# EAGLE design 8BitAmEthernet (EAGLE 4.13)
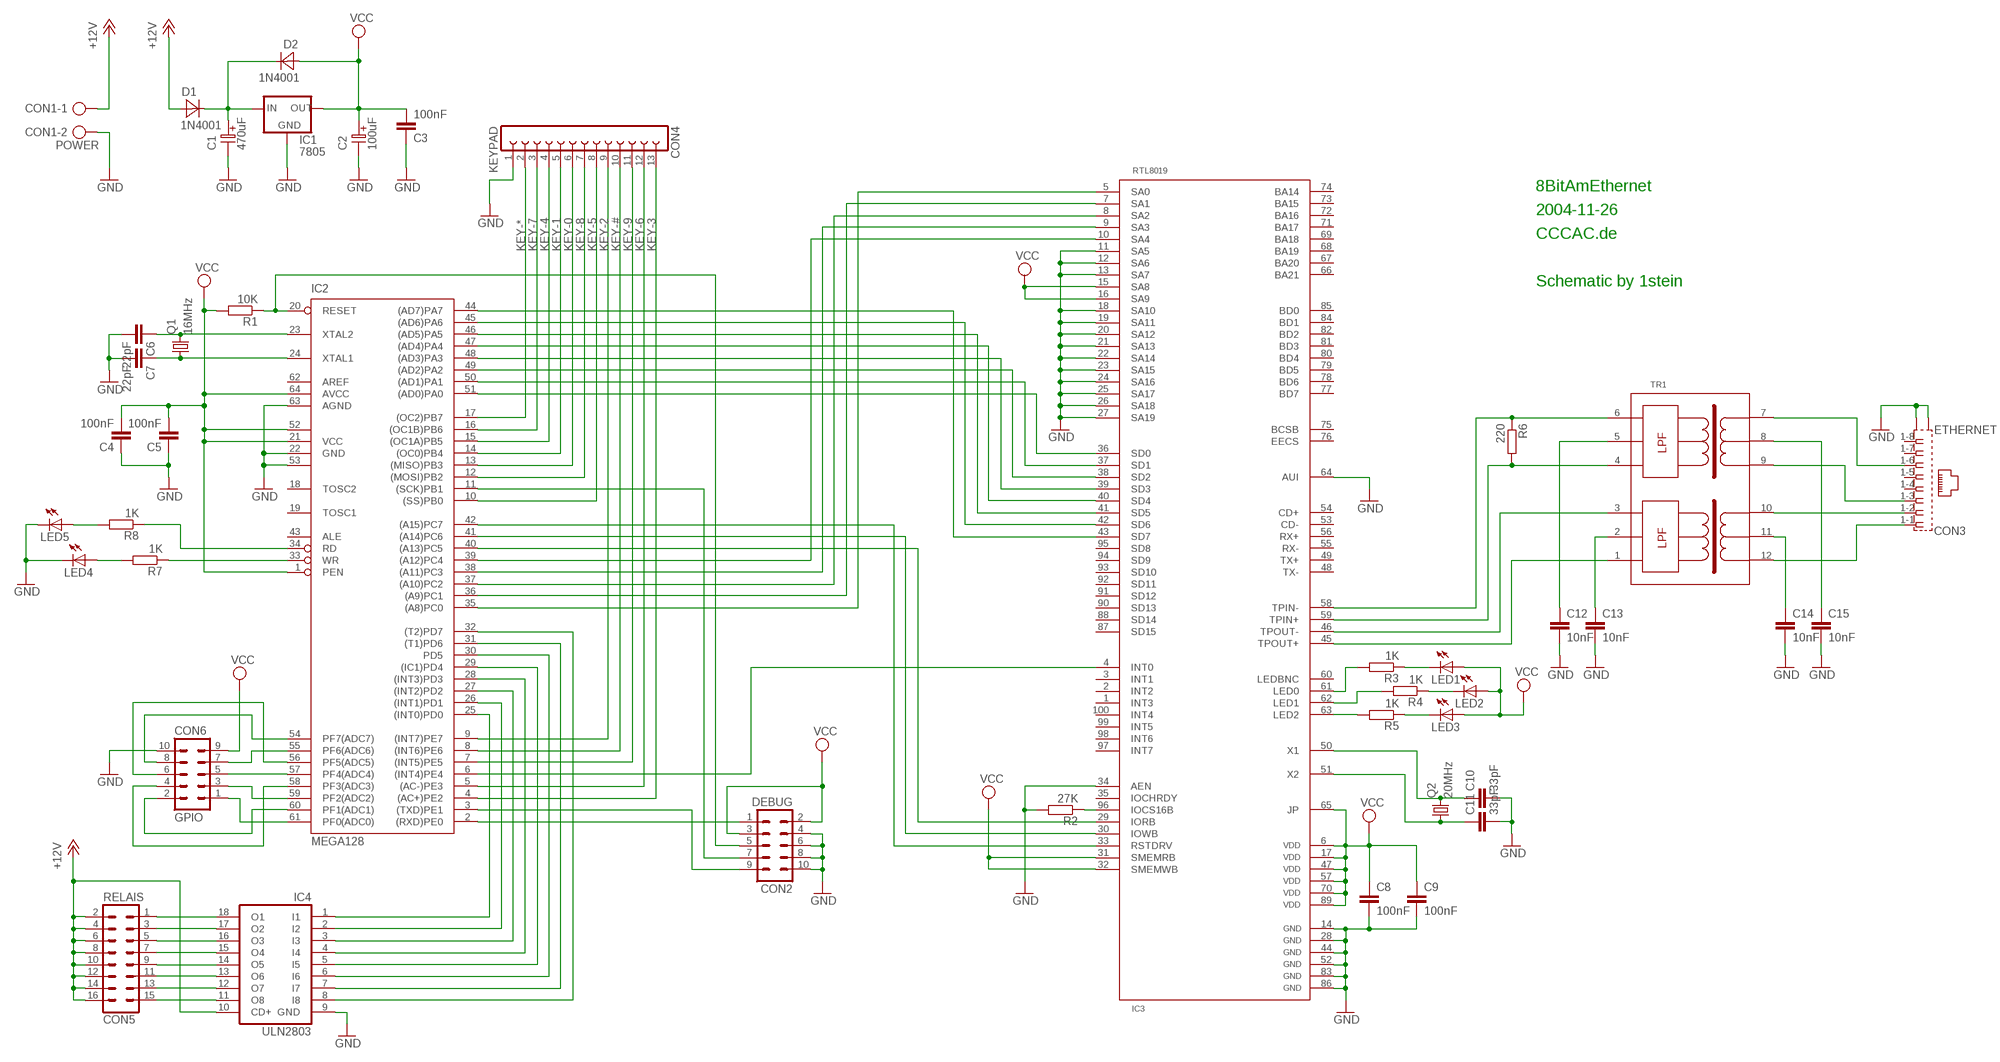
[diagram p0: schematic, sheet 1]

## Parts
C1  470uF  ELC-5  [ES-5]
C2  100uF  ELC-5  [ES-5]
C3  100nF  C-EUC0805  [C0805]
C4  100nF  C-EUC0805  [C0805]
C5  100nF  C-EUC0805  [C0805]
C6  22pF  C-EUC0805  [C0805]
C7  22pF  C-EUC0805  [C0805]
C8  100nF  C-EUC0805  [C0805]
C9  100nF  C-EUC0805  [C0805]
C10  33pF  C-EUC0805  [C0805]
C11  33pF  C-EUC0805  [C0805]
C12  10nF  C-EUC0805  [C0805]
C13  10nF  C-EUC0805  [C0805]
C14  10nF  C-EUC0805  [C0805]
C15  10nF  C-EUC0805  [C0805]
CON1  POWER  AK500/2  [AK500/2]
CON2  DEBUG  ML10  [ML10]
CON3  ETHERNET  557786-1  [557786-1]
CON4  KEYPAD  FE13-1  [FE13]
CON5  RELAIS  ML16  [ML16]
CON6  GPIO  ML10  [ML10]
D1  1N4001  DIODE-7,5  [D-7,5]
D2  1N4001  DIODE-7,5  [D-7,5]
IC1  7805  78XXL  [78XXL]
IC2  MEGA128  MEGA103  [TQFP64]
IC3  RTL8019  [TQPF100]
IC4  ULN2803  ULN2803A  [DIL18]
LED1  LED3MM  [LED3MM]
LED2  LED3MM  [LED3MM]
LED3  LED3MM  [LED3MM]
LED4  LED3MM  [LED3MM]
LED5  LED3MM  [LED3MM]
Q1  16MHz  CRYTALHC49S  [HC49/S]
Q2  20MHz  CRYTALHC49S  [HC49/S]
R1  10K  R-EU_R0805  [R0805]
R2  27K  R-EU_R0805  [R0805]
R3  1K  R-EU_R0805  [R0805]
R4  1K  R-EU_R0805  [R0805]
R5  1K  R-EU_R0805  [R0805]
R6  220  R-EU_R0805  [R0805]
R7  1K  R-EU_R0805  [R0805]
R8  1K  R-EU_R0805  [R0805]
TR1  FB2022  20F001  [DIL16/12]

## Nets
+12V: CON1.1 CON5.2 CON5.4 CON5.6 CON5.8 CON5.10 CON5.12 CON5.14 CON5.16 D1.1(A) IC4.10(CD+)
GND: C1.2 C2.2 C3.1 C4.1 C5.1 C6.2 C7.2 C8.2 C9.2 C10.2 C11.2 C12.2 C13.2 C14.2 C15.2 CON1.2 CON2.4 CON2.6 CON2.8 CON2.10 CON3.G1(S2) CON3.G2(S1) CON4.1 CON6.10 IC1.GND IC2.22(GND) IC2.53(GND1) IC2.63(AGND) IC3.11(SA5) IC3.12(SA6) IC3.13(SA7) IC3.14(G1) IC3.18(SA10) IC3.19(SA11) IC3.20(SA12) IC3.21(SA13) IC3.22(SA14) IC3.23(SA15) IC3.24(SA16) IC3.25(SA17) IC3.26(SA18) IC3.27(SA19) IC3.28(G2) IC3.34(AEN) IC3.44(G3) IC3.52(G4) IC3.64(AUI) IC3.83(G5) IC3.86(G6) IC4.9(GND) LED4.K(C) LED5.K(C) R2.2
KEY-0: CON4.6 IC2.13((MISO)PB3)
KEY-1: CON4.5 IC2.14((OC0)PB4)
KEY-2: CON4.9 IC2.9((INT7)PE7)
KEY-3: CON4.13 IC2.4((AC+)PE2)
KEY-4: CON4.4 IC2.15((OC1A)PB5)
KEY-5: CON4.8 IC2.10((SS)PB0)
KEY-6: CON4.12 IC2.5((AC-)PE3)
KEY-7: CON4.3 IC2.16((OC1B)PB6)
KEY-8: CON4.7 IC2.12((MOSI)PB2)
KEY-9: CON4.11 IC2.7((INT5)PE5)
KEY-#: CON4.10 IC2.8((INT6)PE6)
KEY-*: CON4.2 IC2.17((OC2)PB7)
N$1: C1.1 D1.2(K) D2.2(K) IC1.IN
N$2: C6.1 IC2.23(XTAL2) Q1.2
N$3: C7.1 IC2.24(XTAL1) Q1.1
N$5: CON6.7 IC2.55(PF6(ADC6))
N$7: CON6.4 IC2.58(PF3(ADC3))
N$8: IC3.96(IOCS16B) R2.1
N$9: IC3.61(LED0) R3.2
N$10: IC3.62(LED1) R4.2
N$11: C10.1 IC3.50(X1) Q2.2
N$12: C11.1 IC3.51(X2) Q2.1
N$13: IC3.63(LED2) R5.2
N$14: LED3.K(C) R5.1
N$15: LED2.K(C) R4.1
N$16: LED1.K(C) R3.1
N$17: IC2.35((A8)PC0) IC3.5(SA0)
N$18: CON3.1-1 TR1.12
N$19: IC3.45(TPOUT+) TR1.1
N$20: IC3.46(TPOUT-) TR1.3
N$21: IC3.59(TPIN+) R6.2 TR1.4
N$22: IC3.58(TPIN-) R6.1 TR1.6
N$23: C13.1 TR1.2
N$24: C12.1 TR1.5
N$25: C15.1 TR1.8
N$26: C14.1 TR1.11
N$27: CON3.1-2 TR1.10
N$28: CON3.1-3 TR1.9
N$29: CON3.1-6 TR1.7
N$30: IC2.36((A9)PC1) IC3.7(SA1)
N$31: IC2.37((A10)PC2) IC3.8(SA2)
N$32: IC2.38((A11)PC3) IC3.9(SA3)
N$33: IC2.39((A12)PC4) IC3.10(SA4)
N$34: IC2.40((A13)PC5) IC3.29(IORB)
N$35: IC2.41((A14)PC6) IC3.30(IOWB)
N$36: IC2.42((A15)PC7) IC3.33(RSTDRV)
N$37: IC2.44((AD7)PA7) IC3.43(SD7)
N$38: IC2.45((AD6)PA6) IC3.42(SD6)
N$39: IC2.46((AD5)PA5) IC3.41(SD5)
N$40: IC2.47((AD4)PA4) IC3.40(SD4)
N$41: IC2.48((AD3)PA3) IC3.39(SD3)
N$42: IC2.49((AD2)PA2) IC3.38(SD2)
N$43: IC2.50((AD1)PA1) IC3.37(SD1)
N$44: IC2.51((AD0)PA0) IC3.36(SD0)
N$45: IC2.6((INT4)PE4) IC3.4(INT0)
N$46: IC2.34(RD) R8.1
N$47: LED5.A R8.2
N$48: LED4.A R7.2
N$49: IC2.33(WR) R7.1
N$50: CON5.1 IC4.18(O1)
N$51: CON5.3 IC4.17(O2)
N$52: CON5.5 IC4.16(O3)
N$53: CON5.7 IC4.15(O4)
N$54: CON5.9 IC4.14(O5)
N$55: CON5.11 IC4.13(O6)
N$56: CON5.13 IC4.12(O7)
N$57: CON5.15 IC4.11(O8)
N$58: IC2.25((INT0)PD0) IC4.1(I1)
N$59: IC2.26((INT1)PD1) IC4.2(I2)
N$60: IC2.27((INT2)PD2) IC4.3(I3)
N$61: IC2.28((INT3)PD3) IC4.4(I4)
N$62: IC2.29((IC1)PD4) IC4.5(I5)
N$63: IC2.30(PD5) IC4.6(I6)
N$64: IC2.31((T1)PD6) IC4.7(I7)
N$65: IC2.32((T2)PD7) IC4.8(I8)
N$66: CON6.1 IC2.61(PF0(ADC0))
N$68: CON2.7 IC2.11((SCK)PB1)
N$70: CON2.9 IC2.3((TXD)PE1)
N$71: CON2.1 IC2.2((RXD)PE0)
N$72: CON6.6 IC2.56(PF5(ADC5))
N$73: CON6.8 IC2.54(PF7(ADC7))
N$74: CON2.5 IC2.20(RESET) R1.1
N$75: CON6.2 IC2.60(PF1(ADC1))
N$76: CON6.3 IC2.59(PF2(ADC2))
N$78: CON6.5 IC2.57(PF4(ADC4))
VCC: C2.1 C3.2 C4.2 C5.2 C8.1 C9.1 CON2.2 CON2.3 CON6.9 D2.1(A) IC1.OUT IC2.1(PEN) IC2.21(VCC) IC2.52(VCC1) IC2.64(AVCC) IC3.6(V1) IC3.15(SA8) IC3.16(SA9) IC3.17(V2) IC3.31(SMEMRB) IC3.32(SMEMWB) IC3.47(V3) IC3.57(V4) IC3.65(JP) IC3.70(V5) IC3.89(V6) LED1.A LED2.A LED3.A R1.2
Unconnected: CON3.1-4 CON3.1-5 CON3.1-7 CON3.1-8 IC2.18(TOSC2) IC2.19(TOSC1) IC2.43(ALE) IC2.62(AREF) IC3.1(INT3) IC3.2(INT2) IC3.3(INT1) IC3.35(IOCHRDY) IC3.48(TX-) IC3.49(TX+) IC3.53(CD-) IC3.54(CD+) IC3.55(RX-) IC3.56(RX+) IC3.60(LEDBNC) IC3.66(BA21) IC3.67(BA20) IC3.68(BA19) IC3.69(BA18) IC3.71(BA17) IC3.72(BA16) IC3.73(BA15) IC3.74(BA14) IC3.75(BCSB) IC3.76(EECS) IC3.77(BD7) IC3.78(BD6) IC3.79(BD5) IC3.80(BD4) IC3.81(BD3) IC3.82(BD2) IC3.84(BD1) IC3.85(BD0) IC3.87(SD15) IC3.88(SD14) IC3.90(SD13) IC3.91(SD12) IC3.92(SD11) IC3.93(SD10) IC3.94(SD9) IC3.95(SD8) IC3.97(INT7) IC3.98(INT6) IC3.99(INT5) IC3.100(INT4)

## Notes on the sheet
- 8BitAmEthernet
- 2004-11-26
- CCCAC.de
- Schematic by 1stein

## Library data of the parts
C1 C2 = discrete:ELC-5
C3-C15 = rcl:C-EU: CAPACITOR, European symbol
CON1 = con-ptr500:AK500/2: CONNECTOR
CON2 CON6 = con-harting-ml:ML10: HARTING
CON3 = con-amp:557786-1: AMP connector
CON4 = con-lsta:FE13-1: FEMALE HEADER
CON5 = con-harting-ml:ML16: HARTING
D1 D2 = discrete:DIODE-7,5
IC1 = v-reg:78XXL: VOLTAGE REGULATOR
IC2 = atmel:MEGA103*: MICROCONTROLLER Low-voltage (L) 128 Kbytes FLASH 4 Kbytes SRAM 2 Kbytes EEPROM UART RTC 8-channel 10 bit ADC
IC3 = Realtek:RTL8019
IC4 = uln-udn:ULN2803A: DRIVER ARRAY
LED1-LED5 = led:LED: LED
Q1 Q2 = crystal:CRYTAL: CRYSTAL
R1-R8 = rcl:R-EU_: RESISTOR, European symbol
TR1 = Realtek:20F001

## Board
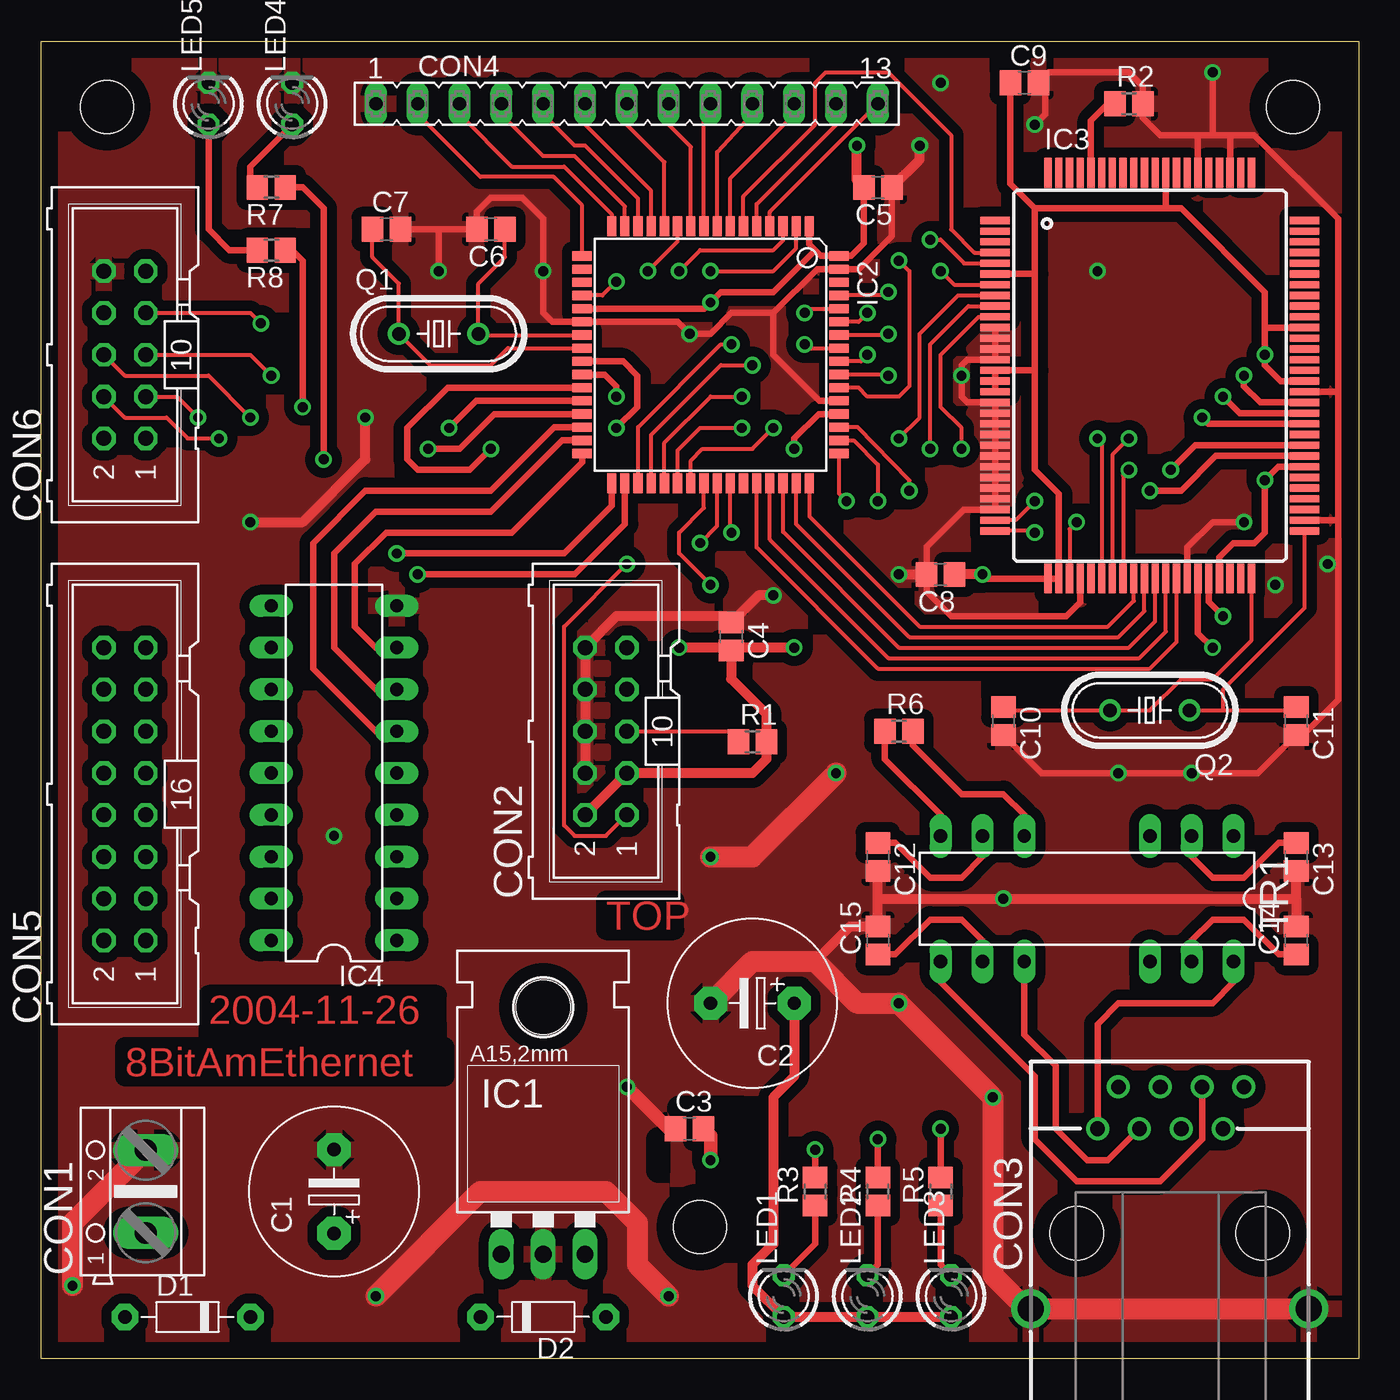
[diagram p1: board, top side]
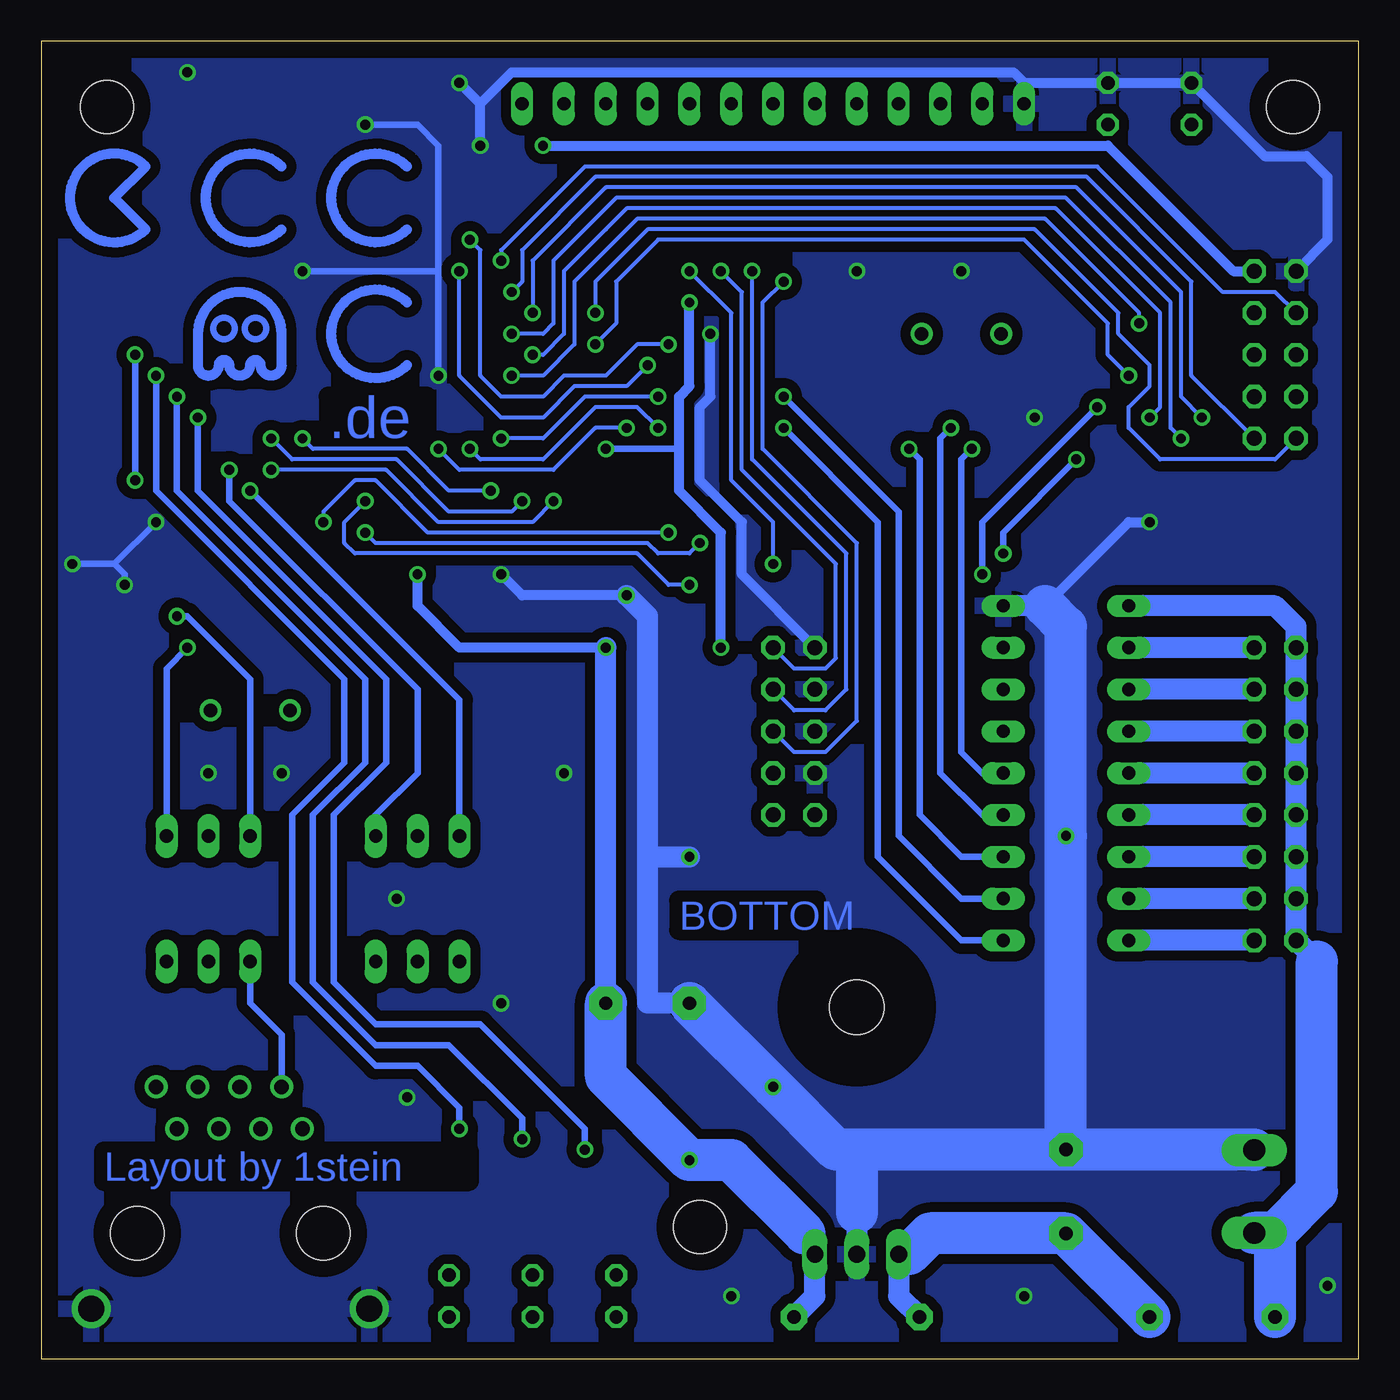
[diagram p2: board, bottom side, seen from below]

Size 80 x 80 mm. Coordinates in mm from the lower left corner, seen from the top.
Outline: 0,0 0,80 80,80 80,0 0,0
Copper layers (1*16): Top 0.035mm / dielectric 1.5mm / Bottom 0.035mm
Design rules "default": minimum track width 10mil, minimum drill 23mil, track to track 8mil, track to pad 8mil, pad to pad 8mil, via to via 8mil, smd to smd 8mil, copper to edge 40mil, drill to drill 8mil, minimum pad ring 10mil, minimum via ring 8mil, stop-mask expansion 4mil, vias tented up to drill 0mil, thermal gap 10mil
Holes 3.2 mm at 76,76 4,76 40,8
tRestrict: 2 lines

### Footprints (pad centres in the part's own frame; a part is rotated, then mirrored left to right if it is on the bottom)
ES-5 = drill 0.813 pad 2.007 octagon: 1 -2.54,0; 2 2.54,0
C0805 = smd 1.3 x 1.5: 1 -0.85,0; 2 0.85,0
AK500/2 = drill 1.321 long: 1 -2.515,0; 2 2.515,0
ML10 = drill 0.914 octagon: 1 -5.08,-1.27; 2 -5.08,1.27; 3 -2.54,-1.27; 4 -2.54,1.27; 5 0,-1.27; 6 0,1.27; 7 2.54,-1.27; 8 2.54,1.27; 9 5.08,-1.27; 10 5.08,1.27
557786-1 = drill 0.889 round: 1-1 -4.445,6.35; 1-2 -3.175,8.89; 1-3 -1.905,6.35; 1-4 -0.635,8.89; 1-5 0.635,6.35; 1-6 1.905,8.89; 1-7 3.175,6.35; 1-8 4.445,8.89 | drill 1.575 pad 2.184 round: G1 -8.509,-4.572; G2 8.382,-4.572 | hole 3.251: -5.715,0; 5.588,0
FE13 = drill 0.813 long: 1 -15.24,0; 2 -12.7,0; 3 -10.16,0; 4 -7.62,0; 5 -5.08,0; 6 -2.54,0; 7 0,0; 8 2.54,0; 9 5.08,0; 10 7.62,0; 11 10.16,0; 12 12.7,0; 13 15.24,0
ML16 = drill 0.914 octagon: 1 -8.89,-1.27; 2 -8.89,1.27; 3 -6.35,-1.27; 4 -6.35,1.27; 5 -3.81,-1.27; 6 -3.81,1.27; 7 -1.27,-1.27; 8 -1.27,1.27; 9 1.27,-1.27; 10 1.27,1.27; 11 3.81,-1.27; 12 3.81,1.27; 13 6.35,-1.27; 14 6.35,1.27; 15 8.89,-1.27; 16 8.89,1.27
D-7,5 = drill 0.813 pad 1.6 octagon: 1 -3.81,0; 2 3.81,0
78XXL = drill 1.016 long: GND 0,-3.81; IN -2.54,-3.81; OUT 2.54,-3.81 | hole 3.302: 0,11.176
TQFP64 = smd 1.194 x 0.559: 1 -7.8,6; 2 -7.8,5.2; 3 -7.8,4.4; 4 -7.8,3.6; 5 -7.8,2.8; 6 -7.8,2; 7 -7.8,1.2; 8 -7.8,0.4; 9 -7.8,-0.4; 10 -7.8,-1.2; 11 -7.8,-2; 12 -7.8,-2.8; 13 -7.8,-3.6; 14 -7.8,-4.4; 15 -7.8,-5.2; 16 -7.8,-6; 33 7.8,-6; 34 7.8,-5.2; 35 7.8,-4.4; 36 7.8,-3.6; 37 7.8,-2.8; 38 7.8,-2; 39 7.8,-1.2; 40 7.8,-0.4; 41 7.8,0.4; 42 7.8,1.2; 43 7.8,2; 44 7.8,2.8; 45 7.8,3.6; 46 7.8,4.4; 47 7.8,5.2; 48 7.8,6 | smd 0.559 x 1.194: 17 -6,-7.8; 18 -5.2,-7.8; 19 -4.4,-7.8; 20 -3.6,-7.8; 21 -2.8,-7.8; 22 -2,-7.8; 23 -1.2,-7.8; 24 -0.4,-7.8; 25 0.4,-7.8; 26 1.2,-7.8; 27 2,-7.8; 28 2.8,-7.8; 29 3.6,-7.8; 30 4.4,-7.8; 31 5.2,-7.8; 32 6,-7.8; 49 6,7.8; 50 5.2,7.8; 51 4.4,7.8; 52 3.6,7.8; 53 2.8,7.8; 54 2,7.8; 55 1.2,7.8; 56 0.4,7.8; 57 -0.4,7.8; 58 -1.2,7.8; 59 -2,7.8; 60 -2.8,7.8; 61 -3.6,7.8; 62 -4.4,7.8; 63 -5.2,7.8; 64 -6,7.8
TQPF100 = smd 1.8 x 0.44: 1 -9.395,9.425; 2 -9.395,8.775; 3 -9.395,8.125; 4 -9.395,7.475; 5 -9.395,6.825; 6 -9.395,6.175; 7 -9.395,5.525; 8 -9.395,4.875; 9 -9.395,4.225; 10 -9.395,3.575; 11 -9.395,2.925; 12 -9.395,2.275; 13 -9.395,1.625; 14 -9.395,0.975; 15 -9.395,0.325; 16 -9.395,-0.325; 17 -9.395,-0.975; 18 -9.395,-1.625; 19 -9.395,-2.275; 20 -9.395,-2.925; 21 -9.395,-3.575; 22 -9.395,-4.225; 23 -9.395,-4.875; 24 -9.395,-5.525; 25 -9.395,-6.175; 26 -9.395,-6.825; 27 -9.395,-7.475; 28 -9.395,-8.125; 29 -9.395,-8.775; 30 -9.395,-9.425; 51 9.395,-9.425; 52 9.395,-8.775; 53 9.395,-8.125; 54 9.395,-7.475; 55 9.395,-6.825; 56 9.395,-6.175; 57 9.395,-5.525; 58 9.395,-4.875; 59 9.395,-4.225; 60 9.395,-3.575; 61 9.395,-2.925; 62 9.395,-2.275; 63 9.395,-1.625; 64 9.395,-0.975; 65 9.395,-0.325; 66 9.395,0.325; 67 9.395,0.975; 68 9.395,1.625; 69 9.395,2.275; 70 9.395,2.925; 71 9.395,3.575; 72 9.395,4.225; 73 9.395,4.875; 74 9.395,5.525; 75 9.395,6.175; 76 9.395,6.825; 77 9.395,7.475; 78 9.395,8.125; 79 9.395,8.775; 80 9.395,9.425 | smd 0.44 x 1.8: 31 -6.175,-12.32; 32 -5.525,-12.32; 33 -4.875,-12.32; 34 -4.225,-12.32; 35 -3.575,-12.32; 36 -2.925,-12.32; 37 -2.275,-12.32; 38 -1.625,-12.32; 39 -0.975,-12.32; 40 -0.325,-12.32; 41 0.325,-12.32; 42 0.975,-12.32; 43 1.625,-12.32; 44 2.275,-12.32; 45 2.925,-12.32; 46 3.575,-12.32; 47 4.225,-12.32; 48 4.875,-12.32; 49 5.525,-12.32; 50 6.175,-12.32; 81 6.175,12.32; 82 5.525,12.32; 83 4.875,12.32; 84 4.225,12.32; 85 3.575,12.32; 86 2.925,12.32; 87 2.275,12.32; 88 1.625,12.32; 89 0.975,12.32; 90 0.325,12.32; 91 -0.325,12.32; 92 -0.975,12.32; 93 -1.625,12.32; 94 -2.275,12.32; 95 -2.925,12.32; 96 -3.575,12.32; 97 -4.225,12.32; 98 -4.875,12.32; 99 -5.525,12.32; 100 -6.175,12.32
DIL18 = drill 0.813 long: 1 -10.16,-3.81; 2 -7.62,-3.81; 3 -5.08,-3.81; 4 -2.54,-3.81; 5 0,-3.81; 6 2.54,-3.81; 7 5.08,-3.81; 8 7.62,-3.81; 9 10.16,-3.81; 10 10.16,3.81; 11 7.62,3.81; 12 5.08,3.81; 13 2.54,3.81; 14 0,3.81; 15 -2.54,3.81; 16 -5.08,3.81; 17 -7.62,3.81; 18 -10.16,3.81
LED3MM = drill 0.813 octagon: A -1.27,0; K 1.27,0
HC49/S = drill 0.813 round: 1 -2.413,0; 2 2.413,0
R0805 = smd 1.3 x 1.5: 1 -0.85,0; 2 0.85,0
DIL16/12 = drill 0.813 long: 1 -8.89,-3.81; 2 -6.35,-3.81; 3 -3.81,-3.81; 4 3.81,-3.81; 5 6.35,-3.81; 6 8.89,-3.81; 7 8.89,3.81; 8 6.35,3.81; 9 3.81,3.81; 10 -3.81,3.81; 11 -6.35,3.81; 12 -8.89,3.81

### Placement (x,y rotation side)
C1  17.78,10.16 90 top
C2  43.18,21.59 180 top
C3  39.37,13.97 0 top
C4  41.9,43.84 270 top
C5  50.8,71.12 180 top
C6  27.3,68.58 180 top
C7  20.95,68.58 0 top
C8  54.61,47.62 180 top
C9  59.69,77.47 0 top
C10  58.42,38.73 270 top
C11  76.2,38.73 270 top
C12  50.8,30.48 270 top
C13  76.2,30.48 270 top
C14  76.2,25.4 90 top
C15  50.8,25.4 90 top
CON1  6.35,10.16 90 top
CON2  34.29,38.1 90 top
CON3  68.58,7.62 0 top
CON4  35.56,76.2 0 top
CON5  5.08,34.29 90 top
CON6  5.08,60.96 90 top
D1  8.89,2.54 0 top
D2  30.48,2.54 180 top
IC1  30.48,10.16 0 top
IC2  40.64,60.96 270 top
IC3  67.31,59.69 0 top
IC4  17.78,35.56 90 top
LED1  45.09,3.81 90 top
LED2  50.16,3.81 90 top
LED3  55.24,3.81 90 top
LED4  15.24,76.2 90 top
LED5  10.16,76.2 90 top
Q1  24.13,62.23 0 top
Q2  67.31,39.37 180 top
R1  43.18,37.47 0 top
R2  66.04,76.2 0 top
R3  46.99,10.16 90 top
R4  50.8,10.16 90 top
R5  54.61,10.16 90 top
R6  52.07,38.1 0 top
R7  13.97,71.12 180 top
R8  13.97,67.31 180 top
TR1  63.5,27.94 180 top

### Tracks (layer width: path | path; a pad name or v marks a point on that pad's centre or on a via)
+12V
  Bottom 1.27: 2.54,24.13 CON5.2 CON5.4 CON5.6 CON5.8 CON5.10 CON5.12 CON5.14 CON5.16 3.81,44.45 5.08,45.72 IC4.10
  Bottom 2.54: 2.54,24.13 2.54,10.16 5.05,7.64 5.08,7.64 | 5.08,7.64 CON1.1 | D1.1 5.08,7.64
GND  (via drill 0.6)
  Top 0.406: C6.2 26.67,68.58 | C6.2 24.13,68.58 | 24.13,68.58 C7.2 | C6.2 26.45,69.64 27.3,70.48 29.21,70.48 30.48,69.22 v30.48,66.04 30.48,63.5 31.02,62.96 IC2.22 38.64,62.96 v39.37,62.23 40.64,62.23 41.91,63.5 44.45,63.5 | C10.2 60.74,35.56 v65.41,35.56 v69.85,35.56 73.88,35.56 C11.2 76.62,37.88 78.74,40.01 78.74,48.26 | 44.45,63.5 47.11,66.16 IC2.63 49.65,66.16 51.65,68.16 C5.1 | 70.23,74.3 IC3.86 | IC3.21 IC3.22 IC3.23 IC3.24 IC3.25 IC3.26 IC3.27 IC3.28 56.01,51.56 53.76,49.31 C8.2 53.76,46.57 55.24,45.09 62.23,45.09 63.09,45.94 IC3.34 | IC3.21 IC3.20 | IC3.11 IC3.12 IC3.13 | IC3.20 IC3.19 IC3.18 56.23,58.06 55.88,58.42 v55.88,59.69 55.88,60.33 56.22,60.66 IC3.14 IC3.13 | IC3.21 IC3.20 | IC3.13 57.91,60.96 | 70.23,74.3 67.94,74.3 66.89,75.35 R2.2 66.89,77.25 66.04,78.11 61.17,78.11 C9.2 60.96,77.05 60.96,75.56 v60.33,74.93 | IC3.44 69.58,49.27 71.12,50.8 v73.03,50.8 | 78.74,50.91 IC3.52 | 72.19,74.3 IC3.83 | 78.74,58.72 IC3.64 | 78.74,58.72 78.74,50.91 | 78.74,50.91 78.74,48.26 | 70.23,74.3 71.12,74.3 | 71.12,74.3 72.19,74.3 | 72.19,74.3 73.66,74.3 78.74,69.22 78.74,58.72 | 78.74,48.26 v78.11,48.26 | IC2.53 47.25,58.16 44.45,60.96 44.45,63.5 | 24.13,68.58 v24.13,66.04 | 71.12,74.3 v71.12,78.11
  Top 0.61: CON2.4 CON2.6 CON2.8 CON2.10 34.92,45.09 41.51,45.09 C4.1 43.56,46.35 v44.45,46.35 | 76.2,29.84 C13.2 76.2,27.94 | 76.2,27.94 C14.2 | 50.8,27.94 C15.2 49.11,26.25 46.99,24.13 | 50.8,27.94 C12.2 | 50.8,27.94 v58.42,27.94 76.2,27.94 | v52.07,47.62 C8.2 | C5.1 53.34,72.81 v53.34,73.66 | v19.68,57.15 19.68,54.61 15.88,50.8 v12.7,50.8
  Top 0.813: C3.1 38.1,13.97 v35.56,16.51
  Top 1.27: CON3.G2 CON3.G1 59.82,3.05 57.78,5.08 v57.78,15.88 v52.07,21.59 49.53,21.59 46.99,24.13 43.18,24.13 C2.2 | v40.64,30.48 43.18,30.48 v48.26,35.56 | v1.91,4.45 1.91,8.26 6.35,12.7 | v20.32,3.81 26.67,10.16 34.29,10.16 36.2,8.26 36.2,5.71 v38.1,3.81
  Bottom 0.406: v78.11,48.26 75.56,48.26 | 75.56,48.26 v73.03,50.8 | v60.33,74.93 57.15,74.93 55.88,73.66 55.88,66.04 | v55.88,59.69 55.88,66.04 | 55.88,66.04 v64.14,66.04 | v74.93,46.99 74.93,47.62 75.56,48.26
  Bottom 0.61: CON2.10 37.47,47.62 37.47,50.8 40.01,53.34 40.01,57.78 39.37,58.42 v39.37,62.23 | CON6.10 1.91,67.94 1.91,71.75 3.17,73.03 5.71,73.03 LED5.K LED4.K 20.32,77.47 | 20.32,77.47 CON4.1 | v44.45,46.35 50.8,46.35 v52.07,47.62 | 20.32,77.47 20.95,78.11 51.44,78.11 53.34,76.2 | v53.34,73.66 53.34,76.2 | 53.34,76.2 v54.61,77.47 | v12.7,50.8 13.97,50.8 19.05,45.72
  Bottom 1.27: 30.48,8.89 IC1.GND | 19.05,45.72 IC4.9 | C2.2 43.18,21.59 43.18,30.48 | 43.18,30.48 43.18,45.09 v44.45,46.35 | 43.18,30.48 v40.64,30.48
  Bottom 2.54: CON1.2 6.35,12.7 C1.2 | 30.48,12.7 30.48,8.89 | C1.2 30.48,12.7 | 19.05,45.72 17.78,44.45 v17.78,31.75 C1.2 | C2.2 v35.56,16.51 31.75,12.7 30.48,12.7
  pour Top (isolate 0.61): -1.27,81.28 81.28,81.28 81.28,-1.27 -1.27,-1.27
  pour Bottom (isolate 0.61): -2.54,82.55 82.55,82.55 82.55,-2.54 -2.54,-2.54
KEY-0
  Top 0.254: CON4.6 33.02,74.93 37.04,70.91 IC2.13
KEY-1
  Top 0.254: IC2.14 36.24,70.44 33.02,73.66 32.38,73.66 30.48,75.56 CON4.5
KEY-2
  Top 0.254: IC2.9 40.24,75.33 CON4.9
KEY-3
  Top 0.254: IC2.4 44.24,69.64 CON4.13
KEY-4
  Top 0.254: IC2.15 35.44,69.97 32.38,73.03 30.48,73.03 27.94,75.56 CON4.4
KEY-5
  Top 0.254: IC2.10 39.44,73.59 38.1,74.93 CON4.8
KEY-6
  Top 0.254: IC2.5 43.44,70.11 48.26,74.93 CON4.12
KEY-7
  Top 0.254: IC2.16 34.64,69.5 31.75,72.39 28.57,72.39 25.4,75.56 CON4.3
KEY-8
  Top 0.254: CON4.7 35.56,74.93 37.84,72.65 IC2.12
KEY-9
  Top 0.254: IC2.7 41.84,71.69 45.72,75.56 CON4.11
KEY-#
  Top 0.254: IC2.8 41.04,73.26 43.18,75.56 CON4.10
KEY-*
  Top 0.254: CON4.2 22.86,75.56 26.67,71.75 31.11,71.75 32.84,70.03 IC2.17
N$1
  Bottom 1.27: 27.3,6.35 IC1.IN 27.94,3.81 D2.2
  Bottom 2.54: D1.2 C1.1 26.04,7.62 27.3,6.35
N$2
  Top 0.254: C6.1 28.16,66.89 26.54,65.28 Q1.2 26.67,62.23 26.74,62.16 IC2.23
N$3
  Top 0.254: IC2.24 28.34,61.36 27.3,60.33 23.62,60.33 Q1.1 21.72,65.28 20.11,66.89 C7.1
N$5  (via drill 0.6)
  Top 0.254: IC2.55 51.37,59.76 v51.44,59.69 | CON6.7 12.7,63.5 v13.34,62.87
  Bottom 0.254: v51.44,59.69 49.53,59.69 47.62,61.59 47.62,65.41 43.81,69.22 19.05,69.22 13.34,63.5 v13.34,62.87
N$7  (via drill 0.6)
  Top 0.254: IC2.58 51.37,62.16 v51.44,62.23 | CON6.4 5.08,57.15 7.62,57.15 8.89,55.88 v10.79,55.88
  Bottom 0.254: v51.44,62.23 49.53,62.23 48.9,62.87 48.9,66.67 45.09,70.48 17.78,70.48 11.43,64.14 11.43,56.52 v10.79,55.88
N$8
  Top 0.406: R2.1 64.77,76.2 63.73,75.17 IC3.96
N$9  (via drill 0.6)
  Top 0.406: IC3.61 70.87,56.77 v70.48,57.15 | R3.2 v46.99,12.7
  Bottom 0.406: v70.48,57.15 70.48,52.7 59.05,41.27 59.05,36.2 62.23,33.02 62.23,22.86 59.69,20.32 53.34,20.32 46.99,13.97 v46.99,12.7
N$10  (via drill 0.6)
  Top 0.406: IC3.62 72.76,57.41 v71.75,58.42 | R4.2 v50.8,13.34
  Bottom 0.406: v71.75,58.42 71.75,52.7 60.33,41.27 60.33,36.2 63.5,33.02 63.5,22.86 59.69,19.05 55.24,19.05 50.8,14.61 v50.8,13.34
N$11
  Top 0.254: IC3.50 73.48,43.64 71.12,41.27 69.22,41.27 67.31,39.37 Q2.2 58.42,39.37 C10.1
N$12
  Top 0.254: IC3.51 76.7,45.59 71.75,40.64 71.75,39.37 | C11.1 76.2,39.37 71.75,39.37 | Q2.1 71.75,39.37
N$13  (via drill 0.6)
  Top 0.406: IC3.63 74.02,58.06 73.03,59.05 v73.03,59.69 | R5.2 v54.61,13.97
  Bottom 0.406: v73.03,59.69 73.03,52.7 61.59,41.27 61.59,36.2 64.77,33.02 64.77,22.86 59.69,17.78 57.15,17.78 54.61,15.24 v54.61,13.97
N$14
  Top 0.406: LED3.K 54.61,5.71 R5.1
N$15
  Top 0.406: R4.1 50.8,5.71 LED2.K
N$16
  Top 0.406: R3.1 46.99,6.99 LED1.K
N$17  (via drill 0.6)
  Top 0.254: v41.91,61.59 41.27,61.59 36.24,56.56 IC2.35 | IC3.5 56.04,66.52 54.61,67.94 v53.98,67.94
  Bottom 0.254: v53.98,67.94 53.34,67.31 53.34,59.69 52.07,58.42 49.53,58.42 48.26,59.69 45.72,59.69 43.81,61.59 v41.91,61.59
N$18
  Top 0.406: CON3.1-1 64.14,20.32 65.41,21.59 71.12,21.59 72.39,22.86 TR1.12
N$19  (via drill 0.6)
  Top 0.406: IC3.45 70.23,44.06 v71.12,43.18
  Bottom 0.406: TR1.1 72.39,41.91 v71.12,43.18
N$20  (via drill 0.6)
  Top 0.406: IC3.46 70.89,45.95 v71.75,45.09
  Bottom 0.406: TR1.3 67.31,41.27 71.12,45.09 v71.75,45.09
N$21  (via drill 0.6)
  Top 0.406: IC3.59 70.07,55.47 v68.58,53.98 | R6.2 52.92,37.25 55.88,34.29 58.42,34.29 59.69,33.02 TR1.4
  Bottom 0.406: v68.58,53.98 68.58,52.07 57.15,40.64 57.15,35.56 59.69,33.02 TR1.4
N$22  (via drill 0.6)
  Top 0.406: IC3.58 71.33,54.81 69.22,52.7 v67.31,52.7 | R6.1 51.22,36.41 54.61,33.02 TR1.6
  Bottom 0.406: v67.31,52.7 54.61,40.01 TR1.6
N$23
  Top 0.406: TR1.2 69.85,30.48 71.12,29.21 73.03,29.21 75.14,31.33 C13.1
N$24
  Top 0.406: TR1.5 57.15,30.48 55.88,29.21 53.98,29.21 51.85,31.33 C12.1
N$25
  Top 0.406: TR1.8 57.15,25.4 55.88,26.67 53.98,26.67 51.85,24.55 C15.1
N$26
  Top 0.406: TR1.11 69.85,25.4 71.12,26.67 73.03,26.67 75.14,24.55 C14.1
N$27
  Bottom 0.406: CON3.1-2 65.41,19.68 67.31,21.59 TR1.10
N$28
  Top 0.406: TR1.9 59.69,19.68 61.59,17.78 61.59,13.97 63.5,12.06 64.77,12.06 CON3.1-3
N$29
  Top 0.406: CON3.1-6 70.48,13.34 67.94,10.79 62.87,10.79 60.33,13.34 60.33,17.14 54.61,22.86 TR1.7
N$30  (via drill 0.6)
  Top 0.254: IC2.36 37.04,56.09 41.27,60.33 v43.18,60.33 | IC3.7 55.44,65.22 v54.61,66.04
  Bottom 0.254: v54.61,66.04 54.61,59.69 52.07,57.15 49.53,57.15 47.62,59.05 44.45,59.05 v43.18,60.33
N$31  (via drill 0.6)
  Top 0.254: IC2.37 37.84,55.62 40.64,58.42 v42.55,58.42 | IC3.8 55.67,64.56 53.34,62.23 53.34,57.15 v52.07,55.88
  Bottom 0.254: v42.55,58.42 46.99,58.42 49.53,55.88 v52.07,55.88
N$32  (via drill 0.6)
  Top 0.254: IC3.9 56.3,63.91 53.98,61.59 v53.98,55.24 | IC2.38 38.64,55.15 40.01,56.52 v42.55,56.52
  Bottom 0.254: v53.98,55.24 53.34,54.61 49.53,54.61 46.35,57.78 43.81,57.78 v42.55,56.52
N$33  (via drill 0.6)
  Top 0.254: IC3.10 56.91,63.27 54.61,60.96 54.61,57.78 55.88,56.52 v55.88,55.24 | IC2.39 39.44,54.54 40.15,55.24 43.18,55.24 v44.45,56.52
  Bottom 0.254: v44.45,56.52 46.35,56.52 48.9,53.98 54.61,53.98 v55.88,55.24
N$34  (via drill 0.6)
  Top 0.254: IC2.40 40.24,51.67 38.73,50.16 38.73,48.9 v40.64,46.99 | IC3.29 59.17,50.91 v60.33,52.07
  Bottom 0.254: v40.64,46.99 41.91,46.99 43.81,48.9 60.96,48.9 61.59,49.53 61.59,50.8 v60.33,52.07
N$35  (via drill 0.6)
  Top 0.254: IC2.41 41.04,50.56 v40.01,49.53 | IC3.30 60.23,50.27 v60.33,50.16
  Bottom 0.254: v40.01,49.53 40.64,48.9 42.55,48.9 43.18,49.53 59.69,49.53 v60.33,50.16
N$36  (via drill 0.6)
  Top 0.254: IC2.42 41.84,50.23 v41.91,50.16 | IC3.33 62.44,50.37 v62.87,50.8
  Bottom 0.254: v41.91,50.16 56.52,50.16 59.69,53.34 60.96,53.34 62.87,51.44 v62.87,50.8
N$37
  Top 0.254: IC2.44 43.44,49.27 50.8,41.91 67.31,41.91 68.94,43.53 IC3.43
N$38
  Top 0.254: IC3.42 68.28,44.16 66.67,42.55 51.44,42.55 44.24,49.74 IC2.45
N$39
  Top 0.254: IC2.46 45.04,50.21 52.07,43.18 66.04,43.18 67.64,44.77 IC3.41
N$40
  Top 0.254: IC2.47 45.84,50.68 52.7,43.81 65.41,43.81 66.98,45.4 IC3.40
N$41
  Top 0.254: IC3.39 66.33,46.02 64.77,44.45 53.34,44.45 46.64,51.15 IC2.48
N$42  (via drill 0.6)
  Top 0.254: IC2.49 48.44,52.52 v48.9,52.07 | IC3.38 65.69,53.62 v66.04,53.98
  Bottom 0.254: v48.9,52.07 50.16,50.8 55.88,50.8 59.05,53.98 v66.04,53.98
N$43  (via drill 0.6)
  Top 0.254: IC2.50 49.33,55.76 50.8,54.29 v50.8,52.07 | IC3.37 65.03,54.88 v66.04,55.88
  Bottom 0.254: v50.8,52.07 51.44,51.44 55.24,51.44 58.42,54.61 64.77,54.61 v66.04,55.88
N$44  (via drill 0.6)
  Top 0.254: IC2.51 49.58,56.56 52.7,53.34 v52.7,52.7 | IC3.36 64.39,55.49 v64.14,55.88
  Bottom 0.254: v52.7,52.7 55.24,52.7 57.78,55.24 63.5,55.24 v64.14,55.88
N$45
  Top 0.254: IC3.4 56.66,67.17 55.24,68.58 55.24,74.3 51.44,78.11 47.62,78.11 46.99,77.47 46.99,74.93 42.64,70.58 IC2.6
N$46  (via drill 0.6)
  Top 0.406: IC2.34 35.44,50.68 32.38,47.62 v22.86,47.62 | R8.1 15.24,67.31 15.88,66.67 v15.88,57.78
  Bottom 0.406: v22.86,47.62 22.86,50.8 v15.88,57.78
N$47
  Top 0.406: LED5.A 10.16,68.58 11.43,67.31 R8.2
N$48
  Top 0.406: R7.2 12.7,71.12 12.7,72.39 LED4.A
N$49  (via drill 0.6)
  Top 0.406: IC2.33 34.64,51.78 31.75,48.9 v21.59,48.9 | R7.1 15.88,71.12 17.14,69.85 v17.14,54.61
  Bottom 0.406: v17.14,54.61 21.59,50.16 v21.59,48.9
N$50
  Bottom 1.27: CON5.1 IC4.18
N$51
  Bottom 1.27: CON5.3 IC4.17
N$52
  Bottom 1.27: CON5.5 IC4.16
N$53
  Bottom 1.27: CON5.7 IC4.15
N$54
  Bottom 1.27: CON5.9 IC4.14
N$55
  Bottom 1.27: CON5.11 IC4.13
N$56
  Bottom 1.27: CON5.13 IC4.12
N$57
  Bottom 1.27: CON5.15 IC4.11
N$58  (via drill 0.6)
  Top 0.406: IC2.25 35.33,60.56 36.2,59.69 36.2,57.78 v34.92,56.52
  Bottom 0.406: IC4.1 24.13,25.4 29.21,30.48 29.21,50.8 v34.92,56.52
N$59  (via drill 0.6)
  Top 0.406: IC2.26 34.22,59.76 34.92,59.05 v34.92,58.42
  Bottom 0.406: IC4.2 24.13,27.94 27.94,31.75 27.94,51.44 v34.92,58.42
N$60  (via drill 0.6)
  Top 0.406: IC2.27 24.67,58.96 22.23,56.52 22.23,54.61 22.86,53.98 26.04,53.98 v27.3,55.24
  Bottom 0.406: IC4.3 24.13,30.48 26.67,33.02 26.67,54.61 v27.3,55.24
N$61  (via drill 0.6)
  Top 0.406: IC2.28 26.41,58.16 v24.77,56.52
  Bottom 0.406: IC4.4 22.86,33.02 25.4,35.56 25.4,55.88 v24.77,56.52
N$62  (via drill 0.6)
  Top 0.406: IC2.29 27.52,57.36 25.4,55.24 v23.5,55.24
  Bottom 0.406: IC4.5 22.86,35.56 24.13,36.83 24.13,54.61 v23.5,55.24
N$63
  Top 0.406: IC4.6 20.32,38.1 16.51,41.91 16.51,49.53 19.68,52.7 27.3,52.7 31.16,56.56 IC2.30
N$64
  Top 0.406: IC4.7 20.32,40.64 17.78,43.18 17.78,48.9 20.32,51.44 27.3,51.44 31.63,55.76 IC2.31
N$65
  Top 0.406: IC4.8 20.32,43.18 19.05,44.45 19.05,48.26 20.95,50.16 28.57,50.16 32.84,54.43 IC2.32
N$66  (via drill 0.6)
  Top 0.254: IC2.61 51.23,64.56 v51.44,64.77
  Bottom 0.254: v51.44,64.77 50.8,65.41 50.8,67.31 46.35,71.75 16.51,71.75 10.16,65.41 10.16,59.69 CON6.1
N$68  (via drill 0.6)
  Top 0.254: IC2.11 38.64,67.85 v36.83,66.04
  Bottom 0.254: CON2.7 34.29,39.37 32.38,39.37 31.11,40.64 31.11,48.9 36.83,54.61 v36.83,66.04
N$69
  Bottom 0.61: 73.66,72.39 arc-270 73.66,68.58 75.56,70.48 73.66,72.39
N$70  (via drill 0.6)
  Top 0.254: IC2.3 45.04,67.9 44.45,67.31 40.01,67.31 v38.73,66.04
  Bottom 0.254: CON2.9 34.29,41.91 32.38,41.91 31.75,42.55 31.75,48.26 37.47,53.98 37.47,64.77 v38.73,66.04
N$71  (via drill 0.6)
  Top 0.254: IC2.2 45.84,67.43 44.45,66.04 v40.64,66.04 | CON2.1 34.29,31.75 32.38,31.75 31.75,32.38 31.75,44.45 v35.56,48.26
  Bottom 0.254: v35.56,48.26 35.56,50.8 38.1,53.34 38.1,63.5 v40.64,66.04
N$72  (via drill 0.6)
  Top 0.254: IC2.56 49.77,60.56 v50.16,60.96 | CON6.6 5.08,59.69 10.16,59.69 v12.7,57.15
  Bottom 0.254: v50.16,60.96 49.53,60.96 48.26,62.23 48.26,66.04 46.35,67.94 | 46.35,67.94 45.72,68.58 | 46.35,67.94 44.45,69.85 18.41,69.85 12.06,63.5 12.06,57.78 v12.7,57.15
N$73  (via drill 0.6)
  Top 0.254: IC2.54 49.62,58.96 50.16,58.42 52.07,58.42 52.7,59.05 52.7,66.04 v52.07,66.67
  Bottom 0.254: v52.07,66.67 52.07,67.31 46.99,72.39 15.88,72.39 8.26,64.77 5.08,64.77 CON6.8
N$74  (via drill 0.6)
  Top 0.254: R1.1 41.7,38.1 CON2.5 | IC2.20 34.08,64.56 v34.92,65.41
  Bottom 0.254: CON2.5 34.29,36.83 32.38,36.83 30.48,38.73 30.48,49.53 36.2,55.24 36.2,64.14 v34.92,65.41
N$75  (via drill 0.6)
  Top 0.254: IC2.60 46.62,63.76 v46.35,63.5
  Bottom 0.254: v46.35,63.5 46.35,65.41 43.18,68.58 19.68,68.58 14.61,63.5 14.61,62.23 12.7,60.33 12.7,59.05 13.97,57.78 13.97,56.52 12.06,54.61 5.08,54.61 CON6.2
N$76  (via drill 0.6)
  Top 0.254: IC2.59 49.62,62.96 v50.16,63.5 | CON6.3 8.26,58.42 v9.53,57.15
  Bottom 0.254: v50.16,63.5 50.16,66.67 45.72,71.12 17.14,71.12 10.79,64.77 10.79,58.42 v9.53,57.15
N$78  (via drill 0.6)
  Top 0.254: IC2.57 46.59,61.36 v46.35,61.59 | CON6.5 12.7,60.96 v13.97,59.69
  Bottom 0.254: v46.35,61.59 45.09,62.87 45.09,65.41 42.55,67.94 20.32,67.94 15.24,62.87 15.24,60.96 v13.97,59.69
N$79
  Bottom 0.61: 65.41,68.58 arc270 65.41,72.39
N$81
  Bottom 0.61: 57.78,68.58 arc270 57.78,72.39
N$82
  Bottom 0.61: 57.78,60.33 arc270 57.78,64.14
N$84
  Bottom 0.61: 65.41,62.23 arc-180 70.48,62.23 70.48,60.33 arc-180 69.22,60.33 arc180 68.58,60.33 arc-180 67.31,60.33 arc180 66.67,60.33 arc-180 65.41,60.33 65.41,62.23
VCC  (via drill 0.6)
  Top 0.406: IC2.21 40.27,63.76 v40.64,64.14 41.27,64.77 44.45,64.77 46.99,67.31 | IC2.1 46.64,67.66 46.99,67.31 | 46.99,67.31 47.34,66.96 IC2.64 49.18,66.96 49.95,67.73 C5.2 | 57.91,59.69 IC3.16 | 57.91,59.69 IC3.17 | 57.91,59.69 IC3.15 60.33,60.02 | 74.3,62.62 IC3.70 | 68.28,69.85 IC3.89 | 60.33,69.85 68.28,69.85 | IC3.31 IC3.32 61.78,52.52 60.33,53.98 60.33,60.02 | IC3.31 57.41,47.37 v57.15,47.62 | C9.1 58.84,71.33 60.33,69.85 | 60.33,65.86 60.33,69.85 | 68.28,69.85 69.22,69.85 74.3,64.77 74.3,62.62 | IC3.65 75.25,59.37 74.3,60.33 v74.3,60.96 74.3,62.62 | IC3.57 75.12,54.16 v74.3,53.34 74.3,50.16 73.66,49.53 72.39,49.53 71.53,48.67 IC3.47 | IC3.31 59.95,47.37 | 60.33,65.86 IC3.6 | 60.33,60.02 60.33,65.86 | IC2.52 47.2,57.36 45.72,55.88 v45.72,55.24
  Top 0.61: LED3.A LED2.A LED1.A 43.18,4.45 43.18,5.71 44.45,6.99 44.45,15.88 45.72,17.14 C2.1 | CON2.2 CON2.3 43.18,35.56 44.03,36.41 R1.2 44.03,39.16 41.9,41.29 C4.2 | C4.2 42.08,43.18 v45.72,43.18 | C4.2 41.9,43.17 41.91,43.18 v38.73,43.18 | v57.15,47.62 C8.1 | C5.2 49.53,71.54 v49.53,73.66
  Top 0.813: v40.64,12.06 40.64,13.55 C3.2
  Bottom 0.406: v74.3,60.96 v74.3,53.34 | 41.27,55.24 v45.72,55.24
  Bottom 0.61: v38.73,43.18 38.73,50.16 41.27,52.7 41.27,55.24 41.27,58.42 40.64,59.05 v40.64,64.14 | v45.72,43.18 54.61,43.18 57.15,45.72 v57.15,47.62 | v49.53,73.66 15.24,73.66 7.62,66.04 CON6.9
  Bottom 1.27: 33.66,7.62 IC1.OUT 33.02,3.81 D2.1 | C2.1 v45.72,43.18
  Bottom 2.54: 33.66,7.62 38.1,12.06 v40.64,12.06 45.72,17.14 C2.1
(copper drawn outside any net)
  shapes: Bottom circle x2

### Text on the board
Top: TOP | 2004-11-26 | 8BitAmEthernet
Bottom: .de | BOTTOM | Layout by 1stein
